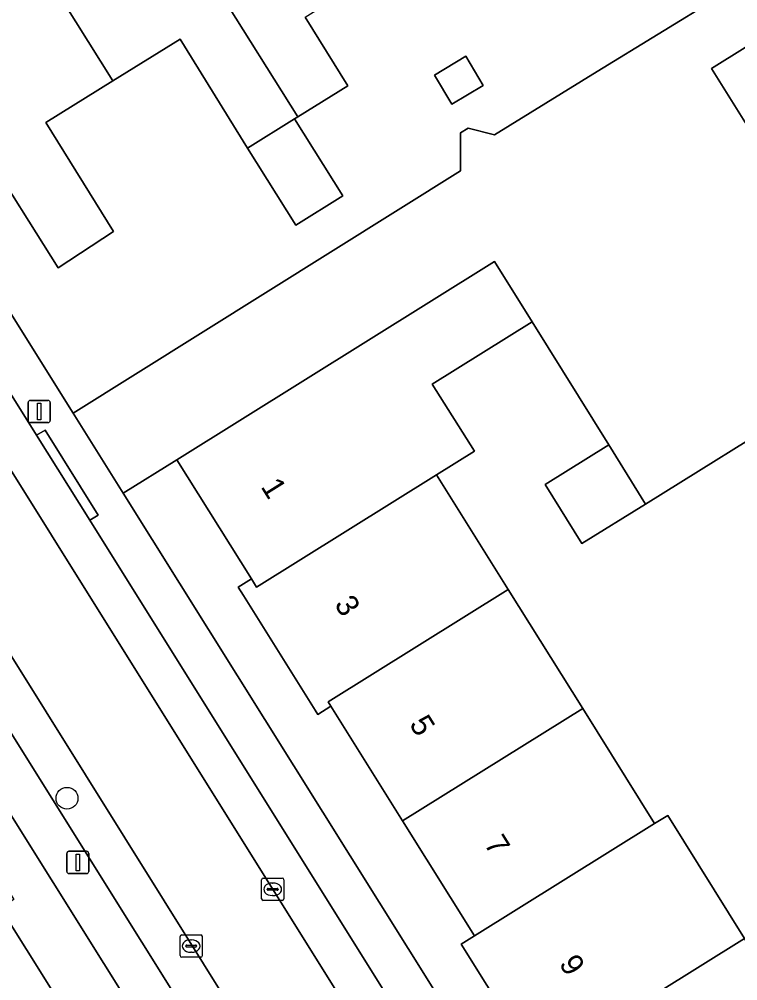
# Model space of a CAD drawing. Extents: x 159664 to 160323, y 385312 to 386115.
# Drawn here: x 159757.41 to 159789.65, y 385878.7 to 385921.86 of the extents above; entities that cross this region are included whole.
import ezdxf

# ---------------------------------------------------------------- set-up
doc = ezdxf.new("R2010")
doc.units = 0
for name, color, linetype in [('IMGEO_Boom', 7, 'Continuous'), ('IMGEO_Erf', 7, 'Continuous'), ('IMGEO_Kolk', 7, 'Continuous'), ('IMGEO_Lichtmast', 7, 'Continuous'), ('IMGEO_Pand', 7, 'Continuous'), ('IMGEO_Pand_nummerreeks', 7, 'Continuous'), ('IMGEO_Parkeervlak_open', 7, 'Continuous'), ('IMGEO_Rijbaan_lokaal_open', 7, 'Continuous'), ('IMGEO_Voetpad_open', 7, 'Continuous')]:
    doc.layers.add(name, color=color, linetype=linetype)

msp = doc.modelspace()

# ---------------------------------------------------------------- linework, layer by layer
at = {"layer": 'IMGEO_Boom'}
msp.add_circle((159759.555, 385886.894), 0.489, dxfattribs=at)
at = {"layer": 'IMGEO_Erf'}
for points in [[(159747.353, 385924.131), (159759.832, 385904.182), (159777.216, 385915.057), (159777.216, 385915.47), (159777.216, 385916.759), (159777.553, 385916.966), (159778.733, 385916.666), (159783.347, 385919.515), (159788.808, 385922.888)], [(159770.238, 385921.956), (159772.155, 385918.867), (159769.908, 385917.474), (159769.765, 385917.385), (159771.926, 385913.935), (159769.825, 385912.62), (159767.659, 385916.078), (159764.628, 385920.964), (159761.617, 385919.097), (159758.603, 385917.227), (159761.635, 385912.341), (159759.153, 385910.707), (159752.414, 385921.411), (159754.457, 385922.693)], [(159791.494, 385921.542), (159788.476, 385919.657), (159793.859, 385911.039)], [(159792.521, 385904.464), (159785.512, 385900.101), (159782.659, 385898.325), (159781.006, 385900.981), (159783.858, 385902.756), (159780.421, 385908.285), (159775.944, 385905.486), (159777.831, 385902.467), (159776.135, 385901.407), (159779.352, 385896.261), (159782.692, 385890.919), (159785.921, 385885.754), (159786.514, 385886.125), (159789.957, 385880.601)], [(159791.799, 385859.713), (159788.568, 385864.879), (159785.226, 385870.22), (159781.999, 385875.376), (159781.883, 385875.561), (159780.697, 385874.82), (159777.238, 385880.349), (159777.832, 385880.72), (159774.615, 385885.877), (159771.397, 385891.031), (159770.803, 385890.661), (159770.686, 385890.851), (159767.471, 385895.998), (159767.235, 385896.373), (159767.829, 385896.744), (159764.489, 385902.087), (159762.082, 385900.584), (159799.061, 385841.468)], [(159788.93, 385835.134), (159751.956, 385894.264), (159749.756, 385892.887), (159753.094, 385887.541), (159753.688, 385887.912), (159757.165, 385882.354), (159756.572, 385881.983), (159756.666, 385881.832), (159759.896, 385876.657)]]:
    msp.add_lwpolyline(points, dxfattribs=at)
msp.add_lwpolyline([(159776.036, 385919.358), (159777.448, 385920.197), (159778.226, 385918.887), (159776.814, 385918.048)], close=True, dxfattribs=at)
at = {"layer": 'IMGEO_Kolk'}
for p, q in [((159768.283, 385882.381), (159768.283, 385883.233)), ((159768.358, 385883.307), (159769.21, 385883.307)), ((159769.284, 385883.233), (159769.284, 385882.381)), ((159768.542, 385882.801), (159768.542, 385882.813)), ((159768.98, 385882.764), (159768.582, 385882.764)), ((159768.585, 385882.85), (159768.983, 385882.85)), ((159768.771, 385883.087), (159768.796, 385883.087)), ((159769.026, 385882.813), (159769.026, 385882.801)), ((159769.21, 385882.307), (159768.358, 385882.307)), ((159768.794, 385882.527), (159768.769, 385882.527)), ((159764.626, 385879.834), (159764.626, 385880.686)), ((159764.701, 385880.76), (159765.553, 385880.76)), ((159765.627, 385880.686), (159765.627, 385879.834)), ((159764.885, 385880.254), (159764.885, 385880.266)), ((159765.323, 385880.217), (159764.925, 385880.217)), ((159764.928, 385880.303), (159765.326, 385880.303)), ((159765.114, 385880.54), (159765.139, 385880.54)), ((159765.369, 385880.266), (159765.369, 385880.254)), ((159765.553, 385879.76), (159764.701, 385879.76)), ((159765.137, 385879.98), (159765.112, 385879.98))]:
    msp.add_line(p, q, dxfattribs=at)
for points in [[(159768.283, 385882.381), (159768.283, 385883.233)], [(159768.358, 385883.307), (159769.21, 385883.307)], [(159769.284, 385883.233), (159769.284, 385882.381)], [(159769.21, 385882.307), (159768.358, 385882.307)], [(159764.626, 385879.834), (159764.626, 385880.686)], [(159764.701, 385880.76), (159765.553, 385880.76)], [(159765.627, 385880.686), (159765.627, 385879.834)], [(159765.553, 385879.76), (159764.701, 385879.76)]]:
    msp.add_lwpolyline(points, dxfattribs=at)
for centre, radius, start, end in [((159768.36, 385883.231), 0.0765, 91.552, 178.448), ((159768.36, 385883.231), 0.0765, 91.552, 178.448), ((159769.208, 385883.231), 0.0765, 1.552, 88.448), ((159769.208, 385883.231), 0.0765, 1.552, 88.448), ((159768.582, 385882.81), 0.0403, 85.8775, 175.7526), ((159768.579, 385882.8), 0.0366, 178.938, 274.7102), ((159768.983, 385882.807), 0.043, 264.8664, 352.4533), ((159768.987, 385882.812), 0.0386, 1.7309, 96.639), ((159768.36, 385882.383), 0.0765, 181.552, 268.448), ((159768.36, 385882.383), 0.0765, 181.552, 268.448), ((159769.208, 385882.383), 0.0765, 271.552, 358.448), ((159769.208, 385882.383), 0.0765, 271.552, 358.448), ((159764.703, 385880.684), 0.0765, 91.552, 178.448), ((159764.703, 385880.684), 0.0765, 91.552, 178.448), ((159765.551, 385880.684), 0.0765, 1.552, 88.448), ((159765.551, 385880.684), 0.0765, 1.552, 88.448), ((159764.925, 385880.263), 0.0403, 85.8775, 175.7526), ((159764.922, 385880.253), 0.0366, 178.938, 274.7102), ((159765.326, 385880.26), 0.043, 264.8664, 352.4533), ((159765.33, 385880.265), 0.0386, 1.7309, 96.639), ((159764.703, 385879.836), 0.0765, 181.552, 268.448), ((159764.703, 385879.836), 0.0765, 181.552, 268.448), ((159765.551, 385879.836), 0.0765, 271.552, 358.448), ((159765.551, 385879.836), 0.0765, 271.552, 358.448)]:
    msp.add_arc(centre, radius, start, end, dxfattribs=at)
for centre, major_axis, ratio, start_param, end_param in [((159768.77, 385882.807), (-0.387, 0.002), 0.722429, 4.712389, 7.853982), ((159768.795, 385882.807), (-0.39, 0.002), 0.717154, 1.570796, 4.712389), ((159765.113, 385880.26), (-0.387, 0.002), 0.722429, 4.712389, 7.853982), ((159765.138, 385880.26), (-0.39, 0.002), 0.717154, 1.570796, 4.712389)]:
    msp.add_ellipse(centre, major_axis=major_axis, ratio=ratio, start_param=start_param, end_param=end_param, dxfattribs=at)
at = {"layer": 'IMGEO_Lichtmast'}
for p, q in [((159757.912, 385904.754), (159758.702, 385904.754)), ((159758.702, 385904.754), (159757.912, 385904.754)), ((159757.812, 385903.854), (159757.812, 385904.654)), ((159757.812, 385904.654), (159757.812, 385903.854)), ((159758.802, 385904.654), (159758.802, 385903.854)), ((159758.802, 385903.854), (159758.802, 385904.654)), ((159758.702, 385903.754), (159757.912, 385903.754)), ((159757.912, 385903.754), (159758.702, 385903.754)), ((159759.645, 385884.512), (159760.435, 385884.512)), ((159760.435, 385884.512), (159759.645, 385884.512)), ((159759.545, 385883.612), (159759.545, 385884.412)), ((159759.545, 385884.412), (159759.545, 385883.612)), ((159760.535, 385884.412), (159760.535, 385883.612)), ((159760.535, 385883.612), (159760.535, 385884.412)), ((159760.435, 385883.512), (159759.645, 385883.512)), ((159759.645, 385883.512), (159760.435, 385883.512))]:
    msp.add_line(p, q, dxfattribs=at)
for points in [[(159758.232, 385904.629), (159758.382, 385904.629), (159758.382, 385903.879), (159758.232, 385903.879), (159758.232, 385904.629)], [(159759.965, 385884.387), (159760.115, 385884.387), (159760.115, 385883.637), (159759.965, 385883.637), (159759.965, 385884.387)]]:
    msp.add_lwpolyline(points, dxfattribs=at)
for centre, start, end in [((159757.912, 385904.654), 90, 180), ((159757.912, 385904.654), 90, 180), ((159758.702, 385904.654), 0, 90), ((159758.702, 385904.654), 360, 90), ((159757.912, 385903.854), 180, 270), ((159757.912, 385903.854), 180, 270), ((159758.702, 385903.854), 270, 0), ((159758.702, 385903.854), 270, 0), ((159759.645, 385884.412), 90, 180), ((159759.645, 385884.412), 90, 180), ((159760.435, 385884.412), 0, 90), ((159760.435, 385884.412), 360, 90), ((159759.645, 385883.612), 180, 270), ((159759.645, 385883.612), 180, 270), ((159760.435, 385883.612), 270, 0), ((159760.435, 385883.612), 270, 0)]:
    msp.add_arc(centre, 0.1, start, end, dxfattribs=at)
at = {"layer": 'IMGEO_Pand'}
for points in [[(159770.238, 385921.956), (159773.294, 385923.873), (159772.179, 385925.649), (159768.201, 385932.001), (159762.888, 385928.682), (159769.908, 385917.474), (159772.155, 385918.867)], [(159762.888, 385928.682), (159757.742, 385925.467), (159757.66, 385925.416), (159761.617, 385919.097), (159764.628, 385920.964), (159767.659, 385916.078), (159769.765, 385917.385), (159769.908, 385917.474)], [(159761.617, 385919.097), (159757.66, 385925.416), (159757.198, 385926.153), (159753.672, 385923.948), (159754.457, 385922.693), (159752.414, 385921.411), (159759.153, 385910.707), (159761.635, 385912.341), (159758.603, 385917.227)], [(159776.036, 385919.358), (159776.814, 385918.048), (159778.226, 385918.887), (159777.448, 385920.197)], [(159769.765, 385917.385), (159767.659, 385916.078), (159769.825, 385912.62), (159771.926, 385913.935)], [(159775.944, 385905.486), (159780.421, 385908.285), (159778.735, 385910.98), (159764.489, 385902.087), (159767.829, 385896.744), (159768.064, 385896.368), (159776.135, 385901.407), (159777.831, 385902.467)], [(159785.512, 385900.101), (159783.858, 385902.756), (159781.006, 385900.981), (159782.659, 385898.325)], [(159779.352, 385896.261), (159776.135, 385901.407), (159768.064, 385896.368), (159767.829, 385896.744), (159767.235, 385896.373), (159767.471, 385895.998), (159770.686, 385890.851), (159770.803, 385890.661), (159771.397, 385891.031), (159771.278, 385891.221)], [(159779.352, 385896.261), (159771.278, 385891.221), (159771.397, 385891.031), (159774.615, 385885.877), (159782.692, 385890.919)], [(159777.832, 385880.72), (159785.921, 385885.754), (159782.692, 385890.919), (159774.615, 385885.877)], [(159786.514, 385886.125), (159785.921, 385885.754), (159777.832, 385880.72), (159777.238, 385880.349), (159780.697, 385874.82), (159781.883, 385875.561), (159789.957, 385880.601)], [(159756.666, 385881.832), (159756.572, 385881.983), (159748.504, 385876.938), (159751.836, 385871.617), (159759.896, 385876.657)], [(159789.957, 385880.601), (159781.883, 385875.561), (159781.999, 385875.376), (159785.226, 385870.22), (159793.289, 385875.254)]]:
    msp.add_lwpolyline(points, close=True, dxfattribs=at)
at = {"layer": 'IMGEO_Parkeervlak_open'}
for points in [[(159744.818, 385921.16), (159786.993, 385853.661)], [(159758.184, 385903.198), (159747.851, 385919.727)], [(159785.139, 385848.258), (159783.248, 385851.302), (159741.032, 385918.933)], [(159741.034, 385915.456), (159751.377, 385898.907), (159753.743, 385895.078), (159790.443, 385836.375), (159792.83, 385832.57), (159829.402, 385773.998), (159831.787, 385770.18), (159850.746, 385739.72), (159852.33, 385740.71), (159841.328, 385758.304), (159807.874, 385811.971), (159785.139, 385848.258)], [(159760.579, 385899.376), (159758.184, 385903.198)], [(159797.238, 385840.688), (159760.579, 385899.376)]]:
    msp.add_lwpolyline(points, dxfattribs=at)
at = {"layer": 'IMGEO_Rijbaan_lokaal_open'}
msp.add_lwpolyline([(159744.818, 385921.16), (159744.511, 385921.664), (159740.787, 385919.315), (159741.032, 385918.933), (159783.248, 385851.302), (159786.993, 385853.661)], close=True, dxfattribs=at)
at = {"layer": 'IMGEO_Voetpad_open'}
for points in [[(159789.716, 385924.506), (159781.447, 385937.53), (159779.772, 385940.197), (159777.865, 385943.241), (159776.606, 385942.453), (159779.266, 385938.206), (159782.956, 385932.362), (159785.983, 385927.461), (159788.808, 385922.888), (159783.347, 385919.515), (159778.733, 385916.666), (159777.553, 385916.966), (159777.216, 385916.759), (159777.216, 385915.47), (159777.216, 385915.057), (159759.832, 385904.182), (159762.082, 385900.584), (159764.489, 385902.087), (159778.735, 385910.98), (159780.421, 385908.285), (159783.858, 385902.756), (159785.512, 385900.101), (159792.521, 385904.464)], [(159801.183, 385838.076), (159799.061, 385841.468), (159762.082, 385900.584), (159759.832, 385904.182), (159747.353, 385924.131), (159744.511, 385921.664), (159744.818, 385921.16)], [(159793.859, 385911.039), (159788.476, 385919.657), (159791.494, 385921.542)], [(159747.851, 385919.727), (159758.184, 385903.198), (159758.579, 385903.421), (159760.952, 385899.606), (159760.579, 385899.376), (159797.238, 385840.688), (159797.62, 385840.926), (159799.98, 385837.147), (159799.599, 385836.908), (159836.21, 385778.296), (159836.589, 385778.536), (159839.001, 385774.716), (159838.62, 385774.468), (159844.984, 385764.305)], [(159741.032, 385918.933), (159740.787, 385919.315), (159737.177, 385917.789), (159749.768, 385897.575), (159749.851, 385897.63), (159751.956, 385894.264), (159788.93, 385835.134), (159789.958, 385833.49), (159791.049, 385831.741), (159827.962, 385772.584), (159830.13, 385769.11), (159843.706, 385747.354)], [(159850.746, 385739.72), (159831.787, 385770.18), (159831.417, 385769.944), (159829.035, 385773.762), (159829.402, 385773.998), (159792.83, 385832.57), (159792.452, 385832.313), (159790.073, 385836.148), (159790.443, 385836.375), (159753.743, 385895.078), (159753.361, 385894.84), (159750.98, 385898.656), (159751.377, 385898.907), (159741.034, 385915.456)]]:
    msp.add_lwpolyline(points, dxfattribs=at)
msp.add_lwpolyline([(159758.184, 385903.198), (159760.579, 385899.376), (159760.952, 385899.606), (159758.579, 385903.421)], close=True, dxfattribs=at)

# ---------------------------------------------------------------- texts
at = {"layer": 'IMGEO_Pand_nummerreeks'}
for s, rotation, p in [('1', 302.0052, (159768.226, 385900.88)), ('3', 302.0052, (159771.526, 385895.6)), ('5', 302.0052, (159774.886, 385890.224)), ('7', 302.0044, (159778.245, 385884.848)), ('9', 302.0052, (159781.605, 385879.472))]:
    msp.add_text(s, height=1, rotation=rotation, dxfattribs=at).set_placement(p)

doc.saveas('drawing.dxf')
